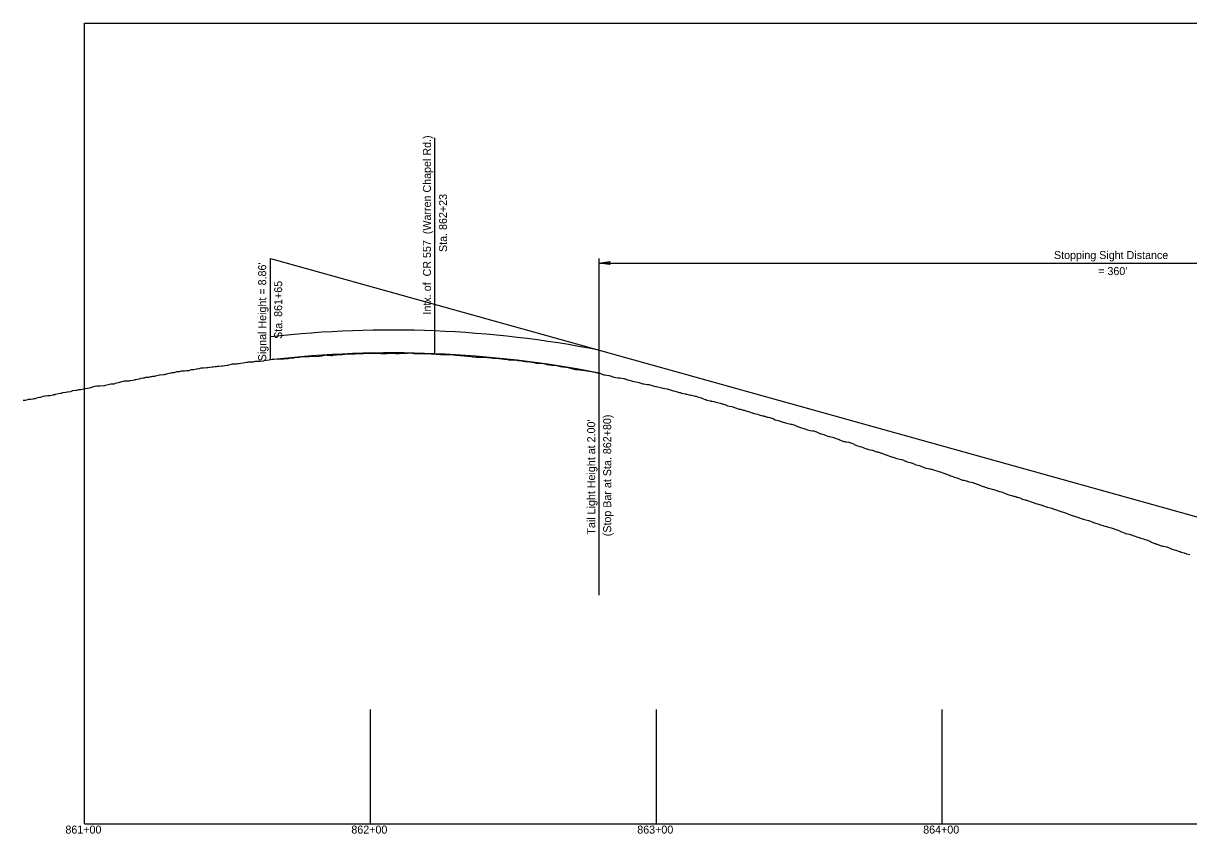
# Model space of a CAD drawing. Extents: x 115987 to 120394, y 324408 to 325987.
# Drawn here: x 119588.7 to 119996.3, y 325283 to 325566.4 of the extents above; entities that cross this region are included whole.
import ezdxf

# ---------------------------------------------------------------- set-up
doc = ezdxf.new("R2010")
doc.units = 0
doc.layers.add('DR_Ditch', color=7, linetype='Continuous')
doc.layers.add('DT_X_Spot_Elev', color=7, linetype='Continuous')

msp = doc.modelspace()

# ---------------------------------------------------------------- linework, layer by layer
at = {"layer": 'DR_Ditch'}
for p, q in [((119610.09, 325286.43), (119610.09, 325566.43)), ((119610.09, 325566.43), (120210.09, 325566.43)), ((119732.66, 325450.85), (119732.66, 325526.43)), ((119675.09, 325448.75), (119675.09, 325484.19)), ((119675.09, 325484.19), (120150.09, 325351.76)), ((119790.09, 325366.43), (119790.09, 325484.13)), ((119790.09, 325482.58), (119793.8, 325483.08)), ((119793.8, 325483.08), (119793.8, 325483.08)), ((119790.09, 325482.58), (120150.09, 325482.58)), ((119793.79, 325482.09), (119790.09, 325482.58)), ((119793.79, 325482.09), (119793.79, 325482.09)), ((119710.09, 325286.43), (119710.09, 325326.43)), ((119810.09, 325286.43), (119810.09, 325326.43)), ((119910.09, 325286.43), (119910.09, 325326.43)), ((119610.09, 325286.43), (120210.09, 325286.43))]:
    msp.add_line(p, q, dxfattribs=at)
for centre, major_axis, ratio, start_param, end_param in [((119794.74, 325482.58), (-1.13, 0), 0.8, 5.69288, 6.856679), ((119717.55, 319462.26), (0, 5996.89), 0.25, 6.234777, 6.311506), ((119717.55, 319462.26), (0, 5988.89), 0.25, 6.234712, 6.311544)]:
    msp.add_ellipse(centre, major_axis=major_axis, ratio=ratio, start_param=start_param, end_param=end_param, dxfattribs=at)
at = {"layer": 'DT_X_Spot_Elev'}
msp.add_lwpolyline([(119588.69, 325434.63), (119589.4, 325434.67), (119590.3, 325434.89), (119590.48, 325434.93), (119590.69, 325434.94), (119591.19, 325434.94), (119591.29, 325434.96), (119592.09, 325435.11), (119592.52, 325435.19), (119592.97, 325435.24), (119593.18, 325435.34), (119593.81, 325435.53), (119594.36, 325435.62), (119594.72, 325435.65), (119595.02, 325435.79), (119595.67, 325436.02), (119596.25, 325436.13), (119596.5, 325436.14), (119597.32, 325436.26), (119597.55, 325436.27), (119597.86, 325436.25), (119598.12, 325436.22), (119599.11, 325436.53), (119599.29, 325436.59), (119599.32, 325436.6), (119599.36, 325436.6), (119599.81, 325436.65), (119599.9, 325436.69), (119600.98, 325436.95), (119601.04, 325436.96), (119601.69, 325437.02), (119602.08, 325437.13), (119602.56, 325437.29), (119603.47, 325437.37), (119603.57, 325437.38), (119604.06, 325437.52), (119604.22, 325437.55), (119605.2, 325437.69), (119605.36, 325437.7), (119605.81, 325437.9), (119605.98, 325437.95), (119607.01, 325438.08), (119607.05, 325438.08), (119607.36, 325438.17), (119607.98, 325438.33), (119608.16, 325438.36), (119608.62, 325438.35), (119608.77, 325438.4), (119610.16, 325438.68), (119610.26, 325438.69), (119610.37, 325438.7), (119611.9, 325438.94), (119611.92, 325438.94), (119611.98, 325438.97), (119613.66, 325439.51), (119613.87, 325439.54), (119614.42, 325439.6), (119615.01, 325439.61), (119615.55, 325439.66), (119616.83, 325439.78), (119617.15, 325439.81), (119617.19, 325439.81), (119617.38, 325439.87), (119618.8, 325440.25), (119619.25, 325440.31), (119620.42, 325440.38), (119620.69, 325440.47), (119621.31, 325440.69), (119622.06, 325440.79), (119622.32, 325440.97), (119622.44, 325440.94), (119623.19, 325441.11), (119623.77, 325441.28), (119624.09, 325441.35), (119624.21, 325441.38), (119624.48, 325441.39), (119625.75, 325441.43), (119626.05, 325441.48), (119626.18, 325441.5), (119626.31, 325441.52), (119627.58, 325441.71), (119627.86, 325441.83), (119628.05, 325441.88), (119629.24, 325442.11), (119629.33, 325442.12), (119629.57, 325442.19), (119629.93, 325442.28), (119630.61, 325442.4), (119631.04, 325442.45), (119631.28, 325442.52), (119631.59, 325442.61), (119632.57, 325442.7), (119632.79, 325442.73), (119633.26, 325442.85), (119633.67, 325442.92), (119633.99, 325442.99), (119634.71, 325443.05), (119634.89, 325443.12), (119636.33, 325443.48), (119636.5, 325443.5), (119636.61, 325443.54), (119637.8, 325443.61), (119638.03, 325443.63), (119638.35, 325443.71), (119638.58, 325443.74), (119639.29, 325443.93), (119639.71, 325444.01), (119639.75, 325444.02), (119640.45, 325444.23), (119640.79, 325444.27), (119641.45, 325444.3), (119641.56, 325444.35), (119642.44, 325444.64), (119642.77, 325444.69), (119643.27, 325444.7), (119644.06, 325444.85), (119644.3, 325444.88), (119644.73, 325444.91), (119645.05, 325444.89), (119645.71, 325444.99), (119646, 325445.03), (119646.62, 325445.05), (119647.55, 325445.31), (119647.68, 325445.35), (119647.7, 325445.35), (119648.27, 325445.34), (119648.37, 325445.37), (119649.33, 325445.62), (119649.5, 325445.65), (119649.95, 325445.64), (119650.94, 325445.88), (119651.28, 325445.92), (119651.66, 325445.89), (119652.93, 325446.05), (119653.11, 325446.08), (119653.24, 325446.08), (119654.65, 325446.26), (119654.9, 325446.31), (119655.08, 325446.32), (119655.8, 325446.42), (119656.22, 325446.45), (119656.65, 325446.51), (119656.78, 325446.51), (119657.22, 325446.49), (119658.16, 325446.66), (119658.38, 325446.69), (119658.45, 325446.69), (119659.15, 325446.71), (119660.02, 325446.9), (119660.14, 325446.92), (119660.16, 325446.92), (119661, 325447.07), (119661.49, 325447.22), (119661.9, 325447.33), (119662.52, 325447.36), (119662.72, 325447.35), (119663.27, 325447.38), (119663.77, 325447.44), (119664.2, 325447.43), (119664.7, 325447.51), (119665.6, 325447.72), (119666.79, 325447.91), (119667.06, 325447.93), (119667.24, 325447.96), (119667.27, 325447.96), (119667.49, 325448.01), (119667.59, 325448.01), (119669.04, 325448.07), (119669.37, 325448.17), (119669.63, 325448.18), (119669.93, 325448.21), (119671.18, 325448.27), (119671.46, 325448.28), (119672.8, 325448.39), (119672.96, 325448.44), (119674.63, 325448.75), (119674.64, 325448.75), (119674.65, 325448.76), (119674.67, 325448.76), (119676.33, 325449.03), (119676.45, 325449.03), (119677.93, 325449.02), (119678.26, 325449.07), (119679.21, 325449.04), (119679.56, 325449.05), (119679.84, 325449.11), (119680.07, 325449.16), (119681.32, 325449.23), (119681.33, 325449.23), (119681.34, 325449.24), (119681.84, 325449.35), (119683.18, 325449.44), (119683.24, 325449.44), (119683.32, 325449.47), (119683.58, 325449.57), (119683.81, 325449.59), (119684.73, 325449.65), (119685.14, 325449.68), (119685.2, 325449.7), (119685.7, 325449.79), (119686.83, 325449.87), (119686.88, 325449.87), (119687.14, 325449.94), (119687.78, 325449.94), (119688.53, 325449.92), (119688.58, 325449.92), (119688.66, 325449.93), (119689.04, 325449.98), (119690, 325450.02), (119690.22, 325450.02), (119690.3, 325450.03), (119690.88, 325449.98), (119691.15, 325449.96), (119691.83, 325449.91), (119692.17, 325449.97), (119693.08, 325450.18), (119693.4, 325450.21), (119693.61, 325450.25), (119694.7, 325450.43), (119694.86, 325450.42), (119695.1, 325450.36), (119696.19, 325450.26), (119696.57, 325450.24), (119696.75, 325450.24), (119697.07, 325450.35), (119698.2, 325450.53), (119698.59, 325450.58), (119699.78, 325450.59), (119699.87, 325450.6), (119700.25, 325450.57), (119700.27, 325450.57), (119701.17, 325450.73), (119701.7, 325450.83), (119701.89, 325450.81), (119701.94, 325450.8), (119701.95, 325450.8), (119701.99, 325450.8), (119703.58, 325450.83), (119703.61, 325450.84), (119704.36, 325450.87), (119704.8, 325450.88), (119705.36, 325450.91), (119705.53, 325450.91), (119707.29, 325450.91), (119707.61, 325450.98), (119708.88, 325451.04), (119709.06, 325451.03), (119709.17, 325451.04), (119710.48, 325451.07), (119710.69, 325451.06), (119711.04, 325451.1), (119711.14, 325451.11), (119712.21, 325451.08), (119712.23, 325451.08), (119712.64, 325451.11), (119712.69, 325451.11), (119712.73, 325451.11), (119713.75, 325450.95), (119714.26, 325450.9), (119714.43, 325450.9), (119715.3, 325450.89), (119715.44, 325450.9), (119715.78, 325450.98), (119716.07, 325451.06), (119717.32, 325451.11), (119717.36, 325451.11), (119717.59, 325451.08), (119718.93, 325450.94), (119719.01, 325450.93), (119719.1, 325450.93), (119719.59, 325450.95), (119720.17, 325450.97), (119720.69, 325451.02), (119721.47, 325451.03), (119722.46, 325451.07), (119722.92, 325451.11), (119723.42, 325451.13), (119724.08, 325451.15), (119724.26, 325451.13), (119724.81, 325451.05), (119725.34, 325451), (119725.93, 325450.94), (119726.09, 325450.91), (119727.12, 325450.98), (119727.25, 325450.99), (119727.28, 325451), (119727.81, 325450.99), (119729.01, 325450.89), (119729.08, 325450.88), (119729.13, 325450.88), (119729.18, 325450.88), (119729.58, 325450.89), (119730.34, 325450.94), (119730.97, 325450.95), (119731.32, 325450.88), (119731.93, 325450.84), (119732.78, 325450.79), (119733.06, 325450.76), (119733.98, 325450.7), (119734.6, 325450.65), (119734.8, 325450.63), (119735.62, 325450.6), (119736.12, 325450.58), (119736.43, 325450.55), (119736.5, 325450.56), (119738.13, 325450.59), (119738.17, 325450.59), (119738.18, 325450.59), (119738.19, 325450.59), (119738.3, 325450.58), (119739.92, 325450.41), (119740.77, 325450.32), (119741.53, 325450.23), (119741.62, 325450.23), (119741.73, 325450.23), (119742.91, 325450.13), (119743.07, 325450.11), (119743.33, 325450.1), (119744.2, 325450.04), (119744.54, 325449.99), (119745.16, 325449.97), (119745.46, 325449.91), (119745.86, 325449.83), (119746.08, 325449.78), (119747.08, 325449.7), (119747.43, 325449.69), (119747.63, 325449.61), (119748.61, 325449.64), (119749.05, 325449.65), (119749.38, 325449.61), (119751.05, 325449.6), (119751.16, 325449.6), (119751.3, 325449.59), (119751.33, 325449.58), (119753.01, 325449.3), (119753.19, 325449.28), (119753.29, 325449.28), (119753.34, 325449.28), (119754.37, 325449.29), (119754.85, 325449.26), (119754.99, 325449.23), (119755.19, 325449.21), (119756.02, 325449.11), (119756.62, 325449.05), (119756.72, 325449.02), (119756.9, 325448.98), (119758.17, 325448.79), (119758.41, 325448.75), (119758.52, 325448.76), (119759.47, 325448.73), (119760.03, 325448.67), (119760.35, 325448.7), (119761.15, 325448.63), (119761.62, 325448.55), (119761.93, 325448.53), (119762.26, 325448.47), (119763.21, 325448.33), (119763.28, 325448.32), (119763.43, 325448.29), (119764.18, 325448.2), (119764.78, 325448.11), (119764.97, 325448.1), (119765.71, 325448.07), (119766.04, 325448.06), (119766.48, 325447.97), (119766.69, 325447.91), (119767.29, 325447.8), (119768.2, 325447.56), (119768.49, 325447.55), (119770.03, 325447.54), (119771.66, 325447.16), (119771.68, 325447.15), (119771.69, 325447.15), (119771.87, 325447.11), (119772.77, 325446.96), (119773.52, 325446.84), (119773.56, 325446.83), (119773.65, 325446.83), (119775.27, 325446.79), (119775.34, 325446.79), (119775.6, 325446.69), (119776.47, 325446.43), (119776.55, 325446.4), (119776.74, 325446.36), (119777.24, 325446.27), (119778.03, 325446.23), (119778.33, 325446.23), (119778.48, 325446.2), (119778.82, 325446.12), (119780.02, 325445.83), (119780.16, 325445.8), (119780.8, 325445.64), (119781.79, 325445.34), (119781.96, 325445.35), (119782.34, 325445.3), (119783.21, 325445.27), (119783.48, 325445.26), (119784.1, 325445.15), (119784.53, 325445.1), (119784.65, 325445.09), (119785.24, 325444.99), (119785.83, 325444.92), (119786.62, 325444.78), (119786.95, 325444.71), (119787.86, 325444.55), (119788.54, 325444.41), (119788.99, 325444.31), (119790.02, 325444.1), (119790.2, 325444.02), (119790.33, 325444.01), (119790.76, 325443.83), (119791.71, 325443.54), (119791.85, 325443.51), (119792.01, 325443.5), (119793.45, 325443.29), (119793.56, 325443.28), (119793.6, 325443.27), (119794.28, 325443.03), (119795.22, 325442.71), (119796.66, 325442.46), (119797.08, 325442.41), (119797.14, 325442.4), (119797.27, 325442.39), (119798.76, 325442.24), (119799.07, 325442.14), (119799.15, 325442.12), (119800.03, 325441.79), (119800.56, 325441.63), (119800.62, 325441.6), (119801.35, 325441.38), (119801.73, 325441.31), (119802.33, 325441.19), (119802.96, 325441.07), (119803.53, 325440.94), (119803.96, 325440.79), (119805.31, 325440.32), (119805.41, 325440.29), (119805.44, 325440.28), (119805.57, 325440.32), (119805.72, 325440.28), (119806.9, 325440.16), (119807.23, 325440.1), (119807.33, 325440.08), (119807.43, 325440.05), (119808.64, 325439.75), (119808.97, 325439.66), (119809.96, 325439.44), (119810.17, 325439.38), (119810.65, 325439.23), (119811.07, 325439.13), (119811.97, 325438.88), (119812.36, 325438.8), (119813.07, 325438.67), (119813.83, 325438.53), (119814.05, 325438.47), (119814.23, 325438.43), (119814.53, 325438.36), (119815.62, 325438.05), (119816.11, 325437.88), (119816.24, 325437.83), (119817.02, 325437.64), (119817.39, 325437.52), (119818.11, 325437.35), (119818.36, 325437.28), (119818.85, 325437.1), (119819.03, 325437.04), (119819.1, 325437.02), (119819.62, 325436.92), (119820.3, 325436.79), (119820.34, 325436.78), (119820.7, 325436.68), (119821.61, 325436.5), (119822.12, 325436.37), (119822.18, 325436.36), (119822.4, 325436.33), (119822.79, 325436.24), (119823.62, 325436.08), (119823.7, 325436.07), (119823.98, 325436.02), (119824.45, 325435.84), (119825.38, 325435.58), (119825.42, 325435.57), (119825.7, 325435.45), (119825.99, 325435.36), (119827.21, 325434.88), (119827.36, 325434.8), (119827.69, 325434.67), (119828.79, 325434.44), (119829.16, 325434.34), (119829.26, 325434.32), (119829.56, 325434.22), (119830.15, 325434.11), (119830.93, 325433.93), (119831.43, 325433.78), (119831.95, 325433.64), (119832.45, 325433.54), (119833.14, 325433.34), (119833.23, 325433.31), (119833.53, 325433.22), (119834.02, 325433.06), (119834.05, 325433.05), (119834.83, 325432.72), (119835.02, 325432.64), (119835.05, 325432.63), (119835.6, 325432.5), (119836.51, 325432.38), (119836.89, 325432.26), (119837.13, 325432.23), (119837.46, 325432.11), (119837.74, 325432), (119838.75, 325431.59), (119839.02, 325431.53), (119839.54, 325431.42), (119840.46, 325431.15), (119840.63, 325431.11), (119840.77, 325431.09), (119841.74, 325430.82), (119842.36, 325430.67), (119842.36, 325430.67), (119843.59, 325430.2), (119843.84, 325430.11), (119843.85, 325430.11), (119844.02, 325430.02), (119844.17, 325429.96), (119845.61, 325429.68), (119845.62, 325429.67), (119845.72, 325429.65), (119846.08, 325429.54), (119846.1, 325429.54), (119847.24, 325429.15), (119847.55, 325429.09), (119847.82, 325429.01), (119847.97, 325428.97), (119848.88, 325428.7), (119849.22, 325428.64), (119849.75, 325428.52), (119850.33, 325428.33), (119850.54, 325428.29), (119851.05, 325428.04), (119851.63, 325427.79), (119852.17, 325427.64), (119852.68, 325427.51), (119853.4, 325427.26), (119853.69, 325427.17), (119853.96, 325427.1), (119854.14, 325427.04), (119855.23, 325426.71), (119855.7, 325426.59), (119855.72, 325426.59), (119855.73, 325426.59), (119857.08, 325426.28), (119857.27, 325426.25), (119857.47, 325426.21), (119857.79, 325426.09), (119858.46, 325425.83), (119859.18, 325425.53), (119860.17, 325425.17), (119860.84, 325424.99), (119861.63, 325424.73), (119862.38, 325424.51), (119862.59, 325424.42), (119862.93, 325424.26), (119863.85, 325424.03), (119863.93, 325424.01), (119864.69, 325423.94), (119864.9, 325423.9), (119865.11, 325423.84), (119865.72, 325423.68), (119865.73, 325423.68), (119865.82, 325423.63), (119866.79, 325423.15), (119867.3, 325422.96), (119867.44, 325422.92), (119868.1, 325422.76), (119868.61, 325422.57), (119869.11, 325422.44), (119869.14, 325422.43), (119869.17, 325422.42), (119870.41, 325421.96), (119870.74, 325421.95), (119870.77, 325421.95), (119870.79, 325421.94), (119872.18, 325421.52), (119872.23, 325421.5), (119873.68, 325420.98), (119873.96, 325420.86), (119874.03, 325420.83), (119874.07, 325420.81), (119874.18, 325420.77), (119875.64, 325420.18), (119875.8, 325420.15), (119875.84, 325420.13), (119876.18, 325420.1), (119876.56, 325420.05), (119877.39, 325419.92), (119877.48, 325419.91), (119878.04, 325419.7), (119878.48, 325419.56), (119878.98, 325419.35), (119879.22, 325419.19), (119879.29, 325419.15), (119879.82, 325418.93), (119880.48, 325418.67), (119880.49, 325418.66), (119881.21, 325418.47), (119881.4, 325418.4), (119882.14, 325418.18), (119882.7, 325417.96), (119883.24, 325417.74), (119883.71, 325417.59), (119883.92, 325417.54), (119884.28, 325417.42), (119885.44, 325417.14), (119885.68, 325417.1), (119886.47, 325416.8), (119887.05, 325416.6), (119887.08, 325416.59), (119887.4, 325416.54), (119887.69, 325416.44), (119887.86, 325416.39), (119888.78, 325416.13), (119888.95, 325416.07), (119889.74, 325415.74), (119889.94, 325415.67), (119890.47, 325415.45), (119890.7, 325415.37), (119890.79, 325415.34), (119891.62, 325415), (119892.34, 325414.81), (119892.49, 325414.78), (119892.78, 325414.71), (119893.31, 325414.54), (119894.22, 325414.26), (119895.15, 325414.01), (119895.78, 325413.88), (119895.9, 325413.84), (119896.51, 325413.59), (119897.23, 325413.3), (119897.33, 325413.25), (119897.82, 325413.01), (119898.69, 325412.82), (119898.84, 325412.77), (119899.15, 325412.7), (119899.61, 325412.57), (119900.33, 325412.24), (119900.47, 325412.17), (119900.61, 325412.13), (119901.48, 325411.93), (119902.09, 325411.77), (119902.3, 325411.69), (119902.85, 325411.42), (119903.32, 325411.28), (119903.8, 325411.05), (119904, 325410.98), (119904.14, 325410.93), (119905.6, 325410.59), (119905.63, 325410.59), (119905.82, 325410.55), (119907.16, 325410.23), (119907.35, 325410.15), (119908.14, 325409.9), (119909.18, 325409.55), (119909.27, 325409.52), (119909.29, 325409.51), (119909.32, 325409.5), (119910.61, 325409.05), (119910.92, 325408.95), (119911.08, 325408.93), (119911.24, 325408.89), (119911.86, 325408.67), (119912.56, 325408.41), (119912.58, 325408.41), (119912.94, 325408.18), (119913.44, 325407.99), (119914.02, 325407.8), (119914.22, 325407.73), (119915.17, 325407.44), (119915.54, 325407.32), (119915.77, 325407.2), (119916.38, 325406.95), (119917.12, 325406.7), (119917.21, 325406.67), (119917.62, 325406.59), (119918.87, 325406.28), (119918.98, 325406.25), (119919.04, 325406.22), (119919.43, 325406.06), (119920.83, 325405.77), (119920.9, 325405.76), (119920.97, 325405.75), (119921.34, 325405.65), (119922.28, 325405.29), (119922.75, 325405.14), (119923.04, 325405.01), (119923.25, 325404.9), (119924.08, 325404.55), (119924.43, 325404.45), (119924.59, 325404.38), (119925.1, 325404.23), (119925.54, 325404.06), (119926.06, 325403.88), (119926.26, 325403.82), (119927.08, 325403.65), (119927.51, 325403.53), (119927.66, 325403.5), (119928.11, 325403.34), (119928.35, 325403.26), (119929.12, 325403), (119929.35, 325402.93), (119930.06, 325402.73), (119930.79, 325402.51), (119931, 325402.47), (119931.64, 325402.2), (119932.37, 325401.89), (119932.72, 325401.74), (119932.98, 325401.64), (119933.36, 325401.53), (119934.25, 325401.25), (119935.02, 325401.08), (119935.39, 325401.01), (119935.83, 325400.87), (119936.08, 325400.78), (119936.21, 325400.75), (119936.34, 325400.7), (119937.52, 325400.3), (119937.84, 325400.11), (119938.09, 325400), (119939.08, 325399.72), (119939.33, 325399.65), (119939.57, 325399.59), (119939.92, 325399.49), (119941.18, 325399.03), (119941.21, 325399.01), (119941.57, 325398.91), (119941.57, 325398.91), (119941.57, 325398.91), (119943.17, 325398.41), (119943.28, 325398.38), (119944.58, 325398.02), (119944.72, 325397.96), (119944.79, 325397.93), (119944.92, 325397.89), (119946.38, 325397.33), (119946.51, 325397.29), (119946.86, 325397.21), (119947.97, 325397.02), (119948.46, 325396.87), (119948.91, 325396.67), (119949.54, 325396.4), (119950.02, 325396.21), (119950.45, 325396.04), (119950.93, 325395.91), (119951.07, 325395.87), (119951.9, 325395.61), (119952.53, 325395.46), (119952.75, 325395.38), (119953.14, 325395.24), (119954.23, 325394.75), (119954.56, 325394.67), (119955.48, 325394.25), (119955.99, 325394.12), (119956.11, 325394.08), (119956.26, 325394.04), (119957.54, 325393.65), (119957.56, 325393.64), (119957.67, 325393.6), (119957.76, 325393.58), (119958.07, 325393.49), (119958.68, 325393.28), (119959.4, 325393.04), (119959.79, 325392.94), (119960.77, 325392.66), (119961.18, 325392.53), (119961.35, 325392.49), (119961.6, 325392.41), (119963.07, 325391.79), (119963.17, 325391.75), (119963.19, 325391.74), (119963.25, 325391.72), (119963.3, 325391.7), (119964.93, 325391.22), (119965.41, 325391.07), (119966.35, 325390.75), (119966.55, 325390.66), (119967.49, 325390.43), (119967.92, 325390.32), (119968.24, 325390.21), (119969.11, 325390), (119969.51, 325389.88), (119969.9, 325389.72), (119970.19, 325389.58), (119970.83, 325389.35), (119971.16, 325389.24), (119971.52, 325389.13), (119972.12, 325388.89), (119972.5, 325388.74), (119972.79, 325388.63), (119974.01, 325388.05), (119974.06, 325388.03), (119974.14, 325388.01), (119975.57, 325387.74), (119975.79, 325387.69), (119975.88, 325387.64), (119976.17, 325387.53), (119977.07, 325387.13), (119977.55, 325387.01), (119978.1, 325386.83), (119978.11, 325386.83), (119978.12, 325386.83), (119978.86, 325386.58), (119979.3, 325386.43), (119979.41, 325386.41), (119980.02, 325386.27), (119980.45, 325386.14), (119980.95, 325385.93), (119981.58, 325385.72), (119981.76, 325385.64), (119982.66, 325385.28), (119982.75, 325385.25), (119982.83, 325385.21), (119983.47, 325384.86), (119984.38, 325384.45), (119984.56, 325384.44), (119984.97, 325384.31), (119985.23, 325384.25), (119985.84, 325384.01), (119986.32, 325383.83), (119986.79, 325383.72), (119987.01, 325383.68), (119987.27, 325383.61), (119988.03, 325383.47), (119988.63, 325383.28), (119988.9, 325383.21), (119989.48, 325382.93), (119989.85, 325382.79), (119990.15, 325382.66), (119990.49, 325382.54), (119990.83, 325382.45), (119991.61, 325382.21), (119991.81, 325382.16), (119993.07, 325381.74), (119993.17, 325381.69), (119993.25, 325381.65), (119993.64, 325381.49), (119994.63, 325381.21), (119994.72, 325381.18), (119995.46, 325380.91), (119995.57, 325380.85), (119996.69, 325380.64)], dxfattribs=at)

# ---------------------------------------------------------------- texts
at = {"layer": 'DR_Ditch'}
for s, rotation, p in [('Intx. of  CR 557  (Warren Chapel Rd.)', 90, (119731.26, 325464.58)), ('Sta. 862+23', 90, (119736.86, 325486.44)), ('Stopping Sight Distance', 360, (119949.15, 325483.98)), ("Signal Height = 8.86'", 90, (119673.63, 325448.22)), ("= 360'", 360, (119964.61, 325478.38)), ('Sta. 861+65', 90, (119679.23, 325456.06)), ("Tail Light Height at 2.00'", 90, (119788.69, 325387.6)), ('(Stop Bar at Sta. 862+80)', 90, (119794.29, 325387.02))]:
    msp.add_text(s, height=2.8, rotation=rotation, dxfattribs=at).set_placement(p)
for s, p in [('861+00', (119603.41, 325283.03)), ('862+00', (119703.41, 325283.03)), ('863+00', (119803.41, 325283.03)), ('864+00', (119903.41, 325283.03))]:
    msp.add_text(s, height=2.8, dxfattribs=at).set_placement(p)

doc.saveas('drawing.dxf')
